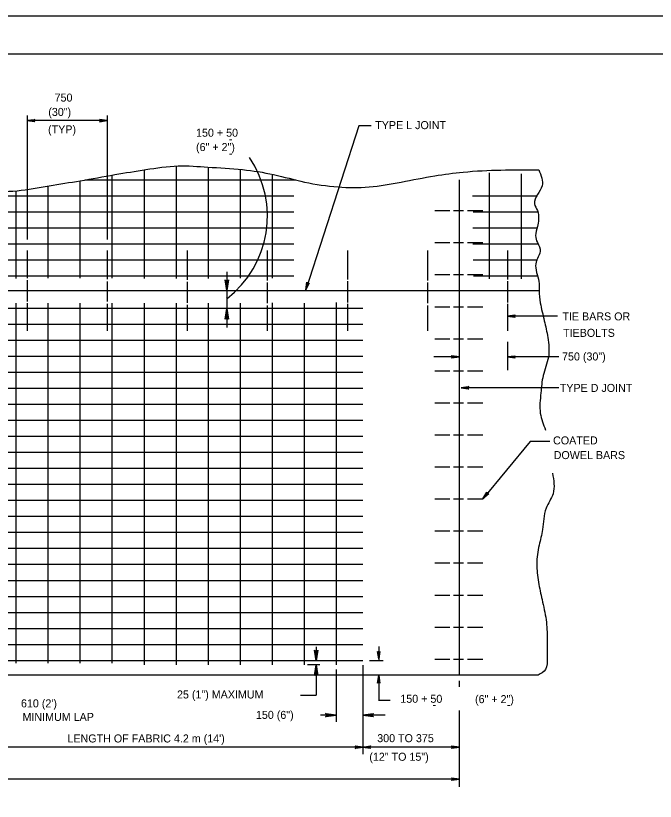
# Model space of a CAD drawing. Extents: x 638703 to 639608, y 298343 to 298937.
# Drawn here: x 639023.6 to 639273.2, y 298630.1 to 298936.6 of the extents above; entities that cross this region are included whole.
import ezdxf

# ---------------------------------------------------------------- set-up
doc = ezdxf.new("R2010")
doc.units = 0
for name, color, linetype in [('1', 7, 'Continuous'), ('2', 7, 'Continuous'), ('3', 7, 'Continuous'), ('PLT-BNDY', 7, 'Continuous')]:
    doc.layers.add(name, color=color, linetype=linetype)

msp = doc.modelspace()

# ---------------------------------------------------------------- linework, layer by layer
at = {"layer": '1'}
msp.add_lwpolyline([(639528.936, 298357.638375), (639528.936, 298921.638375), (638742.936, 298921.638375), (638742.936, 298357.638375), (639528.936, 298357.638375), (639528.936, 298383.997375), (639328.936, 298383.997375), (639328.936, 298448.674875), (639528.936, 298448.674875), (639528.936, 298477.638375), (639328.936, 298477.638375), (639328.936, 298357.638375), (639407.7375, 298357.638375), (639407.7375, 298383.997375), (639407.7375, 298357.638375), (639484.7375, 298357.638375), (639484.7375, 298383.997375), (639484.7375, 298371.680875), (639528.936, 298371.680875)], dxfattribs=at)
at = {"layer": '2'}
for p, q in [((639027.997, 298897.749375), (639027.997, 298849.304875)), ((639059.247, 298897.749375), (639059.247, 298849.304875)), ((639059.247, 298895.699375), (639027.997, 298895.699375)), ((639157.42425, 298893.735875), (639136.772, 298829.639875)), ((639162.343, 298893.735875), (639157.42425, 298893.735875)), ((639073.6325, 298876.317125), (639073.6325, 298834.106625)), ((639086.1325, 298877.785875), (639086.1325, 298834.106625)), ((639098.6325, 298877.289875), (639098.6325, 298834.106625)), ((639111.1325, 298876.417125), (639111.1325, 298834.185875)), ((639061.1325, 298874.333625), (639061.1325, 298834.185875)), ((639123.6325, 298874.789875), (639123.6325, 298834.185875)), ((639208.34525, 298875.385875), (639208.34525, 298833.927375)), ((639220.84525, 298874.889875), (639220.84525, 298833.927375)), ((639036.1325, 298870.050375), (639036.1325, 298834.185875)), ((639048.6325, 298872.171125), (639048.6325, 298834.185875)), ((639132.9305, 298872.456625), (639050.49075, 298872.456625)), ((639196.57, 298872.596125), (639196.57, 298679.356625)), ((639023.6325, 298868.323375), (639023.6325, 298834.085875)), ((639132.068, 298866.206625), (638967.3845, 298866.206625)), ((639227.141, 298866.206625), (639201.866, 298866.206625)), ((639132.068, 298859.956625), (638967.3845, 298859.956625)), ((639187.152, 298860.606625), (639192.9895, 298860.606625)), ((639194.46875, 298860.606625), (639198.33325, 298860.606625)), ((639199.90625, 298860.606625), (639205.902, 298860.606625)), ((639227.141, 298859.956625), (639202.08475, 298859.956625)), ((639132.068, 298853.706625), (638973.6325, 298853.706625)), ((639227.141, 298853.706625), (639201.98475, 298853.706625)), ((639132.068, 298847.456625), (638967.3845, 298847.456625)), ((639187.152, 298848.106625), (639192.9895, 298848.106625)), ((639194.46875, 298848.106625), (639198.33325, 298848.106625)), ((639199.90625, 298848.106625), (639205.902, 298848.106625)), ((639227.141, 298847.456625), (639201.98475, 298847.456625)), ((639027.997, 298844.981625), (639027.997, 298834.204625)), ((639059.247, 298844.981625), (639059.247, 298833.906625)), ((639090.497, 298844.981625), (639090.497, 298833.589875)), ((639121.747, 298844.981625), (639121.747, 298833.292125)), ((639152.997, 298844.981625), (639152.997, 298833.708625)), ((639184.247, 298844.981625), (639184.247, 298833.292125)), ((639215.497, 298844.981625), (639215.497, 298833.708625)), ((639132.068, 298841.206625), (638967.3845, 298841.206625)), ((639227.141, 298841.206625), (639202.08475, 298841.206625)), ((639105.9345, 298836.709125), (639105.9345, 298829.364875)), ((639132.068, 298834.956625), (638967.3845, 298834.956625)), ((639027.997, 298833.452375), (639027.997, 298825.179625)), ((639187.152, 298835.606625), (639192.9895, 298835.606625)), ((639194.46875, 298835.606625), (639198.33325, 298835.606625)), ((639199.90625, 298835.606625), (639205.902, 298835.606625)), ((639227.0995, 298834.956625), (639202.2035, 298834.956625)), ((639059.247, 298832.996125), (639059.247, 298825.179625)), ((639090.497, 298832.835875), (639090.497, 298824.583625)), ((639121.747, 298832.539875), (639121.747, 298824.425375)), ((639152.997, 298833.014875), (639152.997, 298824.762875)), ((639184.247, 298832.539875), (639184.247, 298824.425375)), ((639215.497, 298833.014875), (639215.497, 298824.762875)), ((639227.8345, 298829.356625), (638776.5305, 298829.356625)), ((639105.9345, 298829.364875), (639105.9345, 298822.383625)), ((639023.6325, 298824.525375), (639023.6325, 298684.062875)), ((639027.997, 298824.504625), (639027.997, 298813.731625)), ((639036.1325, 298824.525375), (639036.1325, 298684.062875)), ((639048.6325, 298824.525375), (639048.6325, 298684.062875)), ((639059.247, 298824.250375), (639059.247, 298813.731625)), ((639061.1325, 298824.525375), (639061.1325, 298684.062875)), ((639073.6325, 298824.525375), (639073.6325, 298684.062875)), ((639086.1325, 298824.525375), (639086.1325, 298684.062875)), ((639098.6325, 298824.525375), (639098.6325, 298684.062875)), ((639111.1325, 298824.446125), (639111.1325, 298684.062875)), ((639123.6325, 298824.623375), (639123.6325, 298684.062875)), ((639136.1325, 298824.446125), (639136.1325, 298684.062875)), ((639148.6325, 298824.744125), (639148.6325, 298684.062875)), ((639148.6325, 298824.094125), (639148.6325, 298683.412875)), ((639152.997, 298824.167125), (639152.997, 298813.731625)), ((639215.497, 298824.167125), (639215.497, 298813.731625)), ((639159.07, 298822.456625), (638992.3825, 298822.456625)), ((639073.6325, 298823.875375), (639073.6325, 298683.412875)), ((639086.1325, 298823.875375), (639086.1325, 298683.412875)), ((639090.497, 298823.889875), (639090.497, 298813.731625)), ((639098.6325, 298823.875375), (639098.6325, 298683.412875)), ((639105.9345, 298822.423375), (639105.9345, 298814.933125)), ((639111.1325, 298823.796125), (639111.1325, 298683.412875)), ((639121.747, 298823.512875), (639121.747, 298813.731625)), ((639123.6325, 298823.973375), (639123.6325, 298683.412875)), ((639136.1325, 298823.796125), (639136.1325, 298683.412875)), ((639184.247, 298823.512875), (639184.247, 298813.731625)), ((639187.152, 298823.106625), (639192.9895, 298823.106625)), ((639194.46875, 298823.106625), (639198.33325, 298823.106625)), ((639199.90625, 298823.106625), (639205.902, 298823.106625)), ((639235.0535, 298819.406625), (639215.497, 298819.406625)), ((639159.07, 298816.206625), (638992.3825, 298816.206625)), ((639159.07, 298809.956625), (638992.3825, 298809.956625)), ((639187.152, 298810.606625), (639192.9895, 298810.606625)), ((639194.46875, 298810.606625), (639198.33325, 298810.606625)), ((639199.90625, 298810.606625), (639205.902, 298810.606625)), ((639215.497, 298809.382744), (639215.497, 298798.292523)), ((639159.07, 298803.706625), (638992.3825, 298803.706625)), ((639196.57, 298803.52077), (639186.770386, 298803.52077)), ((639235.50975, 298803.52077), (639215.497, 298803.52077)), ((639159.07, 298797.456625), (638992.3825, 298797.456625)), ((639187.152, 298798.106625), (639192.9895, 298798.106625)), ((639194.46875, 298798.106625), (639198.33325, 298798.106625)), ((639199.90625, 298798.106625), (639205.902, 298798.106625)), ((639159.07, 298791.206625), (638992.3825, 298791.206625)), ((639235.50975, 298791.477375), (639197.364, 298791.477375)), ((639159.07, 298784.956625), (638992.3825, 298784.956625)), ((639187.152, 298785.606625), (639192.9895, 298785.606625)), ((639194.46875, 298785.606625), (639198.33325, 298785.606625)), ((639199.90625, 298785.606625), (639205.902, 298785.606625)), ((639159.07, 298778.706625), (638992.3825, 298778.706625)), ((639159.07, 298772.456625), (638992.3825, 298772.456625)), ((639187.152, 298773.106625), (639192.9895, 298773.106625)), ((639194.46875, 298773.106625), (639198.33325, 298773.106625)), ((639199.90625, 298773.106625), (639205.902, 298773.106625)), ((639224.30525, 298770.571375), (639205.902, 298748.106625)), ((639231.99, 298770.571375), (639224.30525, 298770.571375)), ((639159.07, 298766.206625), (638992.3825, 298766.206625)), ((639159.07, 298759.956625), (638992.3825, 298759.956625)), ((639187.152, 298760.606625), (639192.9895, 298760.606625)), ((639194.46875, 298760.606625), (639198.33325, 298760.606625)), ((639199.90625, 298760.606625), (639205.902, 298760.606625)), ((639159.07, 298753.706625), (638992.3825, 298753.706625)), ((639159.07, 298747.456625), (638992.3825, 298747.456625)), ((639187.152, 298748.106625), (639192.9895, 298748.106625)), ((639194.46875, 298748.106625), (639198.33325, 298748.106625)), ((639199.90625, 298748.106625), (639205.902, 298748.106625)), ((639159.07, 298741.206625), (638992.3825, 298741.206625)), ((639187.152, 298735.606625), (639192.9895, 298735.606625)), ((639194.46875, 298735.606625), (639198.33325, 298735.606625)), ((639199.90625, 298735.606625), (639205.902, 298735.606625)), ((639159.07, 298734.956625), (638992.3825, 298734.956625)), ((639159.07, 298728.706625), (638992.3825, 298728.706625)), ((639187.152, 298723.106625), (639192.9895, 298723.106625)), ((639194.46875, 298723.106625), (639198.33325, 298723.106625)), ((639199.90625, 298723.106625), (639205.902, 298723.106625)), ((639159.07, 298722.456625), (638992.3825, 298722.456625)), ((639159.07, 298716.206625), (638992.3825, 298716.206625)), ((639159.07, 298709.956625), (638992.3825, 298709.956625)), ((639187.15125, 298710.606625), (639192.9845, 298710.606625)), ((639194.46175, 298710.606625), (639198.3305, 298710.606625)), ((639196.57, 298710.606625), (639196.57, 298710.606625)), ((639196.57, 298710.606625), (639196.57, 298710.606625)), ((639196.57, 298710.606625), (639196.57, 298710.606625)), ((639196.57, 298710.606625), (639196.57, 298710.606625)), ((639196.57, 298710.606625), (639196.57, 298710.606625)), ((639196.57, 298710.606625), (639196.57, 298710.606625)), ((639196.57, 298710.606625), (639196.57, 298710.606625)), ((639196.57, 298710.606625), (639196.57, 298710.606625)), ((639196.57, 298710.606625), (639196.57, 298710.606625)), ((639196.57, 298710.606625), (639196.57, 298710.606625)), ((639196.57, 298710.606625), (639196.57, 298710.606625)), ((639196.57, 298710.606625), (639196.57, 298710.606625)), ((639196.57, 298710.606625), (639196.57, 298710.606625)), ((639199.91375, 298710.606625), (639205.90125, 298710.606625)), ((639159.07, 298703.706625), (638992.3825, 298703.706625)), ((639159.07, 298697.456625), (638992.3825, 298697.456625)), ((639187.1525, 298698.106625), (639192.9795, 298698.106625)), ((639194.4545, 298698.106625), (639198.3295, 298698.106625)), ((639196.57125, 298698.106625), (639196.57125, 298698.106625)), ((639196.57125, 298698.106625), (639196.57125, 298698.106625)), ((639196.57125, 298698.106625), (639196.57125, 298698.106625)), ((639196.57125, 298698.106625), (639196.57125, 298698.106625)), ((639196.57125, 298698.106625), (639196.57125, 298698.106625)), ((639196.57125, 298698.106625), (639196.57125, 298698.106625)), ((639196.57125, 298698.106625), (639196.57125, 298698.106625)), ((639196.57125, 298698.106625), (639196.57125, 298698.106625)), ((639196.57125, 298698.106625), (639196.57125, 298698.106625)), ((639196.57125, 298698.106625), (639196.57125, 298698.106625)), ((639196.57125, 298698.106625), (639196.57125, 298698.106625)), ((639196.57125, 298698.106625), (639196.57125, 298698.106625)), ((639196.57125, 298698.106625), (639196.57125, 298698.106625)), ((639196.57125, 298698.106625), (639196.57125, 298698.106625)), ((639199.92125, 298698.106625), (639205.9025, 298698.106625)), ((639159.07, 298691.206625), (638992.3825, 298691.206625)), ((639140.845, 298690.406125), (639140.845, 298684.921125)), ((639165.2105, 298690.523375), (639165.2105, 298684.956625)), ((639159.07, 298684.906625), (638992.3825, 298684.906625)), ((639073.6325, 298684.956625), (639073.6325, 298684.956625)), ((639073.6325, 298684.956625), (639073.6325, 298684.956625)), ((639142.30325, 298683.412875), (639137.4095, 298683.412875)), ((639140.845, 298683.373375), (639140.845, 298671.567125)), ((639159.095, 298684.956625), (639157.17425, 298684.956625)), ((639159.07, 298683.192125), (639159.07, 298648.537875)), ((639167.03, 298684.956625), (639161.6805, 298684.956625)), ((639187.15175, 298685.606625), (639192.9745, 298685.606625)), ((639194.4475, 298685.606625), (639198.32675, 298685.606625)), ((639196.5705, 298685.606625), (639196.5705, 298685.606625)), ((639196.5705, 298685.606625), (639196.5705, 298685.606625)), ((639196.5705, 298685.606625), (639196.5705, 298685.606625)), ((639196.5705, 298685.606625), (639196.5705, 298685.606625)), ((639196.5705, 298685.606625), (639196.5705, 298685.606625)), ((639196.5705, 298685.606625), (639196.5705, 298685.606625)), ((639196.5705, 298685.606625), (639196.5705, 298685.606625)), ((639196.5705, 298685.606625), (639196.5705, 298685.606625)), ((639196.5705, 298685.606625), (639196.5705, 298685.606625)), ((639196.5705, 298685.606625), (639196.5705, 298685.606625)), ((639196.5705, 298685.606625), (639196.5705, 298685.606625)), ((639196.5705, 298685.606625), (639196.5705, 298685.606625)), ((639196.5705, 298685.606625), (639196.5705, 298685.606625)), ((639196.5705, 298685.606625), (639196.5705, 298685.606625)), ((639196.5705, 298685.606625), (639196.5705, 298685.606625)), ((639199.92875, 298685.606625), (639205.90175, 298685.606625)), ((639148.6325, 298681.504625), (639148.6325, 298661.112875)), ((639227.43475, 298679.356625), (638775.4805, 298679.356625)), ((639165.2105, 298679.356625), (639165.2105, 298669.404625)), ((639196.57, 298677.091875), (639196.57, 298674.724875)), ((639134.73675, 298671.567125), (639140.845, 298671.567125)), ((639169.64375, 298669.404625), (639165.1855, 298669.404625)), ((639196.57, 298665.579125), (639196.57, 298647.410875)), ((639196.57, 298665.101625), (639196.57, 298635.814875)), ((639148.6325, 298663.731625), (639142.46175, 298663.731625)), ((639167.73275, 298663.731625), (639159.07, 298663.731625)), ((639196.57, 298651.231625), (638992.3825, 298651.231625)), ((639196.57, 298651.231625), (639159.07, 298651.231625)), ((639196.57, 298638.731625), (638793.622, 298638.731625))]:
    msp.add_line(p, q, dxfattribs=at)
for points in [[(639030.8345, 298895.343125), (639030.72825, 298895.549375), (639027.997, 298895.699375), (639030.8345, 298895.343125), (639030.98025, 298895.218125), (639027.997, 298895.699375), (639030.72625, 298895.834875), (639030.82625, 298896.036875), (639027.997, 298895.699375), (639030.98025, 298896.174375), (639030.82625, 298896.036875)], [(639056.4095, 298895.343125), (639056.51575, 298895.549375), (639059.247, 298895.699375), (639056.4095, 298895.343125), (639056.26375, 298895.218125), (639059.247, 298895.699375), (639056.51775, 298895.834875), (639056.41775, 298896.036875), (639059.247, 298895.699375), (639056.26375, 298896.174375), (639056.41775, 298896.036875)], [(639106.43325, 298833.337375), (639106.1445, 298833.188625), (639105.9345, 298829.364875), (639106.43325, 298833.337375), (639106.60825, 298833.541875), (639105.9345, 298829.364875), (639105.74525, 298833.185875), (639105.462, 298833.325875), (639105.9345, 298829.364875), (639105.2695, 298833.541875), (639105.462, 298833.325875)], [(639137.9825, 298832.231625), (639137.75325, 298832.194125), (639136.772, 298829.639875), (639137.9825, 298832.231625), (639138.145, 298832.331625), (639136.772, 298829.639875), (639137.4805, 298832.279625), (639137.318, 298832.437875), (639136.772, 298829.639875), (639137.23675, 298832.625375), (639137.318, 298832.437875)], [(639105.43575, 298818.395125), (639105.7245, 298818.543875), (639105.9345, 298822.367625), (639105.43575, 298818.395125), (639105.26075, 298818.191125), (639105.9345, 298822.367625), (639106.12425, 298818.547125), (639106.407, 298818.407125), (639105.9345, 298822.367625), (639106.5995, 298818.191125), (639106.407, 298818.407125)], [(639218.3345, 298819.050375), (639218.22825, 298819.256625), (639215.497, 298819.406625), (639218.3345, 298819.050375), (639218.4805, 298818.925375), (639215.497, 298819.406625), (639218.22625, 298819.542125), (639218.32625, 298819.744125), (639215.497, 298819.406625), (639218.4805, 298819.881625), (639218.32625, 298819.744125)], [(639193.7325, 298803.87702), (639193.83875, 298803.67077), (639196.57, 298803.52077), (639193.7325, 298803.87702), (639193.5865, 298804.00202), (639196.57, 298803.52077), (639193.84075, 298803.38527), (639193.74075, 298803.18327), (639196.57, 298803.52077), (639193.5865, 298803.04577), (639193.74075, 298803.18327)], [(639218.3345, 298803.16452), (639218.22825, 298803.37077), (639215.497, 298803.52077), (639218.3345, 298803.16452), (639218.4805, 298803.03952), (639215.497, 298803.52077), (639218.22625, 298803.65627), (639218.32625, 298803.85827), (639215.497, 298803.52077), (639218.4805, 298803.99577), (639218.32625, 298803.85827)], [(639200.2015, 298791.121125), (639200.09525, 298791.327375), (639197.364, 298791.477375), (639200.2015, 298791.121125), (639200.34725, 298790.996125), (639197.364, 298791.477375), (639200.09325, 298791.612875), (639200.19325, 298791.814875), (639197.364, 298791.477375), (639200.34725, 298791.952375), (639200.19325, 298791.814875)], [(639207.977, 298750.075375), (639207.75, 298750.125375), (639205.902, 298748.106625), (639207.977, 298750.075375), (639208.1645, 298750.110875), (639205.902, 298748.106625), (639207.527, 298750.304625), (639207.43325, 298750.510875), (639205.902, 298748.106625), (639207.427, 298750.715125), (639207.43325, 298750.510875)], [(639141.34375, 298688.893625), (639141.055, 298688.744875), (639140.845, 298684.921125), (639141.34375, 298688.893625), (639141.51875, 298689.098125), (639140.845, 298684.921125), (639140.65525, 298688.742125), (639140.3725, 298688.882125), (639140.845, 298684.921125), (639140.18, 298689.098125), (639140.3725, 298688.882125)], [(639165.56675, 298688.487875), (639165.3605, 298688.381625), (639165.2105, 298685.650375), (639165.56675, 298688.487875), (639165.69175, 298688.633625), (639165.2105, 298685.650375), (639165.075, 298688.379625), (639164.873, 298688.479625), (639165.2105, 298685.650375), (639164.7355, 298688.633625), (639164.873, 298688.479625)], [(639140.34625, 298679.400875), (639140.635, 298679.549625), (639140.845, 298683.373375), (639140.34625, 298679.400875), (639140.17125, 298679.196375), (639140.845, 298683.373375), (639141.03475, 298679.552375), (639141.3175, 298679.412375), (639140.845, 298683.373375), (639141.51, 298679.196375), (639141.3175, 298679.412375)], [(639141.08675, 298680.694125), (639140.845, 298682.723375), (639141.168, 298680.694125)], [(639164.85425, 298676.367125), (639165.0605, 298676.473375), (639165.2105, 298679.204625), (639164.85425, 298676.367125), (639164.72925, 298676.221125), (639165.2105, 298679.204625), (639165.34575, 298676.475375), (639165.548, 298676.375375), (639165.2105, 298679.204625), (639165.6855, 298676.221125), (639165.548, 298676.375375)], [(639144.66, 298664.230375), (639144.80875, 298663.941625), (639148.6325, 298663.731625), (639144.66, 298664.230375), (639144.456, 298664.405375), (639148.6325, 298663.731625), (639144.8115, 298663.541875), (639144.6715, 298663.259125), (639148.6325, 298663.731625), (639144.456, 298663.066625), (639144.6715, 298663.259125)], [(639163.0425, 298663.232875), (639162.89375, 298663.521625), (639159.07, 298663.731625), (639163.0425, 298663.232875), (639163.2465, 298663.057875), (639159.07, 298663.731625), (639162.891, 298663.921375), (639163.031, 298664.204125), (639159.07, 298663.731625), (639163.2465, 298664.396625), (639163.031, 298664.204125)], [(639156.2325, 298651.587875), (639156.33875, 298651.381625), (639159.07, 298651.231625), (639156.2325, 298651.587875), (639156.08675, 298651.712875), (639159.07, 298651.231625), (639156.34075, 298651.096125), (639156.24075, 298650.894125), (639159.07, 298651.231625), (639156.08675, 298650.756625), (639156.24075, 298650.894125)], [(639161.9075, 298650.875375), (639161.80125, 298651.081625), (639159.07, 298651.231625), (639161.9075, 298650.875375), (639162.05325, 298650.750375), (639159.07, 298651.231625), (639161.79925, 298651.367125), (639161.89925, 298651.569125), (639159.07, 298651.231625), (639162.05325, 298651.706625), (639161.89925, 298651.569125)], [(639193.7325, 298651.587875), (639193.83875, 298651.381625), (639196.57, 298651.231625), (639193.7325, 298651.587875), (639193.58675, 298651.712875), (639196.57, 298651.231625), (639193.84075, 298651.096125), (639193.74075, 298650.894125), (639196.57, 298651.231625), (639193.58675, 298650.756625), (639193.74075, 298650.894125)], [(639193.7325, 298639.087875), (639193.83875, 298638.881625), (639196.57, 298638.731625), (639193.7325, 298639.087875), (639193.58675, 298639.212875), (639196.57, 298638.731625), (639193.84075, 298638.596125), (639193.74075, 298638.394125), (639196.57, 298638.731625), (639193.58675, 298638.256625), (639193.74075, 298638.394125)]]:
    msp.add_lwpolyline(points, dxfattribs=at)
msp.add_arc((639080.79854, 298858.508929), 40.978891, 307.83879722, 33.77902222, dxfattribs=at)
for points in [[(638776.49075, 298874.669125), (638781.2325, 298876.119125), (638786.445, 298874.669125), (638793.8075, 298872.727375), (638800.593, 298871.754625), (638806.3845, 298872.231625), (638811.22425, 298874.652375), (638818.0095, 298875.623375), (638824.297, 298874.175375), (638830.08875, 298872.727375), (638836.872, 298873.700375), (638842.66575, 298875.623375), (638849.44925, 298873.700375), (638855.73675, 298872.727375), (638862.50125, 298874.175375), (638873.6305, 298874.175375), (638885.7305, 298871.279625), (638897.8095, 298869.831625), (638911.8555, 298871.279625), (638923.4595, 298874.175375), (638936.51175, 298876.119125), (638949.08675, 298877.567125), (638961.18675, 298875.148375), (638974.24075, 298872.727375), (638987.31175, 298871.279625), (638998.91575, 298869.831625), (639011.493, 298868.362875), (639024.068, 298868.362875), (639036.645, 298870.306625), (639048.745, 298872.231625), (639062.293, 298874.652375), (639074.37425, 298876.596125), (639086.94925, 298878.044125), (639098.57425, 298877.567125), (639112.122, 298876.596125), (639124.20325, 298874.652375), (639136.30325, 298871.754625), (639149.3555, 298869.831625), (639161.4555, 298869.831625), (639174.0325, 298871.754625), (639187.10325, 298874.175375), (639198.21175, 298875.623375), (639227.687, 298876.508625)], [(639227.687, 298876.508625), (639228.964, 298870.248375), (639227.141, 298866.856625), (639226.0265, 298863.264875), (639227.141, 298860.606625), (639227.59525, 298857.156625), (639227.141, 298854.356625), (639226.464, 298850.848375), (639227.141, 298848.106625), (639228.289, 298844.737875), (639227.141, 298841.856625), (639226.464, 298839.104625), (639227.0995, 298835.606625), (639227.83275, 298832.102375), (639227.83275, 298829.385875), (639228.289, 298824.644125), (639229.85575, 298817.642125), (639231.20575, 298811.096125), (639231.44325, 298803.419125), (639229.3995, 298796.198375), (639228.50775, 298789.433625), (639228.289, 298781.519125), (639230.359, 298774.967375)], [(639233.04275, 298758.144375), (639233.24725, 298750.137875), (639230.53075, 298744.485875), (639229.18075, 298736.133625), (639227.83275, 298730.044125), (639226.92025, 298722.823375), (639227.59525, 298715.604625), (639228.964, 298708.819125), (639230.53075, 298700.925375), (639230.987, 298693.467125), (639230.987, 298686.246125), (639230.312, 298681.504625), (639227.43475, 298679.356625)]]:
    msp.add_spline(points, degree=3, dxfattribs=at)
at = {"layer": 'PLT-BNDY'}
msp.add_lwpolyline([(638702.936, 298936.638375), (639543.936, 298936.638375), (639543.936, 298342.638375), (638702.936, 298342.638375)], close=True, dxfattribs=at)

# ---------------------------------------------------------------- texts
at = {"layer": '1'}
msp.add_text('(12" TO 15")', height=3.1249995, dxfattribs=at).set_placement((639161.567607, 298645.941375))
at = {"layer": '2'}
msp.add_text('.', height=3.124998, rotation=99, dxfattribs=at).set_placement((639106.2845, 298826.012875))
at = {"layer": '3'}
for s, height, p in [('750', 3.1249995, (639038.73775, 298903.132375)), ('(30")', 3.1249995, (639036.275305, 298897.535875)), ('TYPE L JOINT', 3.1249995, (639163.87825, 298892.387875)), ('(TYP)', 3.1249995, (639036.18725, 298890.735875)), ('150 + 50', 3.1249995, (639093.93875, 298889.420625)), ('-', 3.124999, (639106.705, 298887.042375)), ('(6" + 2")', 3.1249995, (639093.93875, 298883.824375)), ('-', 3.124999, (639106.705, 298881.446125)), ('TIE BARS OR ', 3.1249995, (639236.91675, 298817.763375)), ('TIEBOLTS', 3.1249995, (639237.17275, 298811.338375)), ('750 (30")', 3.1249995, (639236.775922, 298802.131445)), ('TYPE D JOINT', 3.1249995, (639235.88475, 298789.850375)), ('COATED', 3.1249995, (639233.275, 298769.375375)), ('DOWEL BARS', 3.1249995, (639233.5125, 298763.642125)), ('25 (1") MAXIMUM', 3.1249995, (639086.5135, 298670.244125)), ('150 + 50', 3.1249995, (639173.66575, 298668.567125)), ('(6" + 2")', 3.1249995, (639202.8225, 298668.424125)), ("610 (2')", 3.1249995, (639025.616, 298666.769375)), ('150 (6")', 3.1249995, (639117.31125, 298662.283125)), ('-', 3.124999, (639186.2755, 298666.288375)), ('-', 3.124999, (639215.27175, 298666.288375)), ('MINIMUM LAP', 3.1249995, (639026.20775, 298661.493875)), ("LENGTH OF FABRIC 4.2 m (14')", 3.1249995, (639043.7495, 298653.083625)), ('300 TO 375', 3.1249995, (639164.645774, 298653.192375))]:
    msp.add_text(s, height=height, dxfattribs=at).set_placement(p)

doc.saveas('drawing.dxf')
